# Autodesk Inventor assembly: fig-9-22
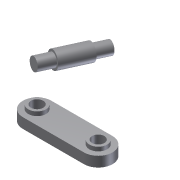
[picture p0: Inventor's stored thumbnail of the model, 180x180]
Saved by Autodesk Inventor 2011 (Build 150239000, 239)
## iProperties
Shininess: 64.0
Length Units: 11269
Angle Units: 11279
Time Units: 11290
Mass Units: 11283
Length Display Precision: 3
Angle Display Precision: 2
Created: 2002-01
Part Number: fig-9-22
Document SubType Name: Assembly
Designer: ***
Density: 0.0
Volumn: 0.0
Area: 0.0
PropertySet Name: Model Information
Control State: 0
Master: False
Checked Out: False
Author: ***
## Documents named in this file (3)
- C:\Users\CADSoft\Desktop\part files\c09-inv-2011-prt\fig-9-22.iam
- C:\Users\CADSoft\Desktop\inventor\c09-inv-2010-prt\c09\Part5.ipt
- C:\Users\CADSoft\Desktop\inventor\c09-inv-2010-prt\c09\Part6.ipt
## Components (2 placed, 2 different names)
1. Part5:1
2. Part6:1
